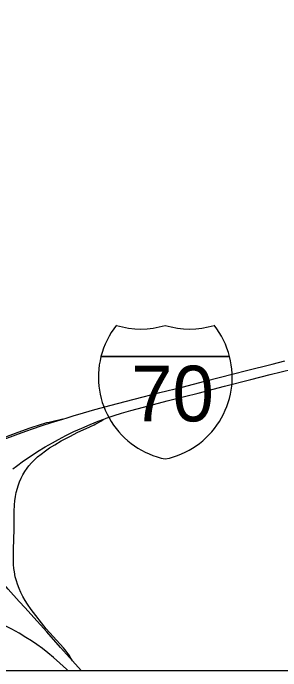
# Model space of a CAD drawing. Extents: x -29.6 to 34, y 0 to 22.
# Drawn here: x -22.655 to -22.122, y 1.053 to 2.363 of the extents above; entities that cross this region are included whole.
import ezdxf

# ---------------------------------------------------------------- set-up
doc = ezdxf.new("R2010")
doc.units = 0
for name, color, linetype in [('GM_X_Interchange_Ramps', 7, 'Continuous'), ('GM_X_Interstate_Route', 7, 'Continuous'), ('GM_X_Interstate_Shield', 7, 'Continuous'), ('SH_Text', 7, 'Continuous')]:
    doc.layers.add(name, color=color, linetype=linetype)

msp = doc.modelspace()

# ---------------------------------------------------------------- linework, layer by layer
at = {"layer": 'GM_X_Interchange_Ramps'}
for points in [[(-22.556, 1.5546), (-22.578, 1.5493), (-22.5835, 1.548), (-22.5887, 1.5468), (-22.5945, 1.5451), (-22.5995, 1.5435), (-22.6236, 1.5355), (-22.651, 1.5258), (-22.6817, 1.5148)], [(-22.5369, 1.0724), (-22.539, 1.0761), (-22.5414, 1.0803), (-22.5431, 1.0831), (-22.5453, 1.0864), (-22.5475, 1.0894), (-22.5497, 1.0923), (-22.555, 1.0984), (-22.5756, 1.1214), (-22.589, 1.1368), (-22.5986, 1.1485), (-22.6101, 1.1631), (-22.6192, 1.1752), (-22.6265, 1.1858), (-22.6311, 1.1932), (-22.6355, 1.2008), (-22.6397, 1.209), (-22.6432, 1.217), (-22.6464, 1.2252), (-22.6487, 1.2324), (-22.6508, 1.2402), (-22.6527, 1.25), (-22.6535, 1.2569), (-22.6541, 1.2644), (-22.6545, 1.2766), (-22.6543, 1.2953), (-22.6534, 1.3343), (-22.6529, 1.3704), (-22.6522, 1.3837), (-22.6515, 1.3918), (-22.6503, 1.4005), (-22.6488, 1.4085), (-22.6467, 1.417), (-22.6453, 1.4214), (-22.6423, 1.4296), (-22.639, 1.437), (-22.6355, 1.4437), (-22.6316, 1.4502), (-22.6273, 1.4565), (-22.6237, 1.4611), (-22.6184, 1.4673), (-22.6123, 1.4735), (-22.6063, 1.479), (-22.5992, 1.4849), (-22.5908, 1.4912), (-22.5826, 1.4969), (-22.5723, 1.5034), (-22.5591, 1.5109), (-22.5422, 1.52), (-22.5261, 1.5282), (-22.5098, 1.5359), (-22.4939, 1.5431), (-22.4901, 1.545), (-22.485, 1.5479), (-22.4806, 1.5505), (-22.4756, 1.5535), (-22.4725, 1.5553)]]:
    msp.add_lwpolyline(points, dxfattribs=at)
at = {"layer": 'GM_X_Interstate_Route'}
for points in [[(-22.4921, 1.5737), (-22.4894, 1.5745), (-22.4624, 1.5817), (-22.4139, 1.5941), (-22.3625, 1.6072), (-22.3185, 1.6184), (-22.2733, 1.6299), (-22.2163, 1.6444), (-22.1898, 1.6512), (-22.139, 1.6641), (-22.1136, 1.6705)], [(-22.3138, 1.5993), (-22.2866, 1.6063), (-22.2336, 1.6199), (-22.1817, 1.6332), (-22.1427, 1.6431), (-22.0993, 1.6543)], [(-22.4725, 1.5553), (-22.4698, 1.5563), (-22.4539, 1.5618), (-22.4389, 1.5666), (-22.4209, 1.5718), (-22.3956, 1.5785), (-22.3482, 1.5906), (-22.3138, 1.5993)], [(-22.556, 1.5546), (-22.5474, 1.5573), (-22.5352, 1.561), (-22.5151, 1.5671), (-22.4921, 1.5737)], [(-22.7877, 1.4729), (-22.7508, 1.4864), (-22.7151, 1.4991), (-22.6495, 1.5231), (-22.6298, 1.5302), (-22.599, 1.5408), (-22.5785, 1.5475), (-22.556, 1.5546)], [(-22.6557, 1.4554), (-22.6487, 1.4608), (-22.6345, 1.471), (-22.6215, 1.4799), (-22.6063, 1.4897), (-22.5914, 1.4989), (-22.5768, 1.5074), (-22.5646, 1.5141), (-22.5501, 1.5216), (-22.5339, 1.5296), (-22.5185, 1.5367), (-22.5019, 1.5439), (-22.4857, 1.5504), (-22.4725, 1.5553)], [(-22.5369, 1.0724), (-22.5609, 1.0993), (-22.5882, 1.1303), (-22.6197, 1.1654), (-22.6314, 1.1784), (-22.6428, 1.1908), (-22.6651, 1.2154), (-22.6865, 1.2393), (-22.6994, 1.2535), (-22.7087, 1.2639), (-22.7169, 1.273), (-22.7181, 1.2743), (-22.7279, 1.285), (-22.7381, 1.2962), (-22.7467, 1.3057), (-22.7553, 1.3152), (-22.7642, 1.3252), (-22.7693, 1.3308), (-22.7732, 1.3352), (-22.7743, 1.3365), (-22.7774, 1.3399), (-22.7814, 1.3444)], [(-22.5455, 1.0528), (-22.549, 1.0562), (-22.5618, 1.0681), (-22.575, 1.0796), (-22.5863, 1.0889), (-22.5969, 1.0971), (-22.6082, 1.1053), (-22.6188, 1.1125), (-22.6296, 1.1195), (-22.6431, 1.1276), (-22.6579, 1.1358), (-22.6724, 1.1433), (-22.6818, 1.1479), (-22.6966, 1.1547), (-22.7077, 1.1595)], [(-22.5191, 1.0528), (-22.5318, 1.0667), (-22.5369, 1.0724)]]:
    msp.add_lwpolyline(points, dxfattribs=at)
at = {"layer": 'GM_X_Interstate_Shield'}
for p, q in [((-22.48, 1.6789), (-22.2239, 1.6789)), ((-22.2239, 1.6789), (-22.48, 1.6789)), ((-22.2239, 1.6789), (-22.48, 1.6789))]:
    msp.add_line(p, q, dxfattribs=at)
for centre, start, end in [((-22.3187, 1.6381), 141.669, 165.8066), ((-22.4006, 1.9005), 253.0091, 286.9909), ((-22.3033, 1.9005), 253.0091, 286.9909), ((-22.3852, 1.6381), 14.1934, 38.331), ((-22.3187, 1.6381), 165.8066, 258.463), ((-22.3852, 1.6381), 281.537, 14.1934)]:
    msp.add_arc(centre, 0.1665, start, end, dxfattribs=at)
at = {"layer": 'SH_Text'}
msp.add_lwpolyline([(-29.5833, 13.2079), (-10.7478, 13.2079), (-10.7478, 1.0528), (-29.5833, 1.0528)], close=True, dxfattribs=at)

# ---------------------------------------------------------------- texts
at = {"layer": 'GM_X_Interstate_Shield'}
msp.add_text('70', height=0.11097, dxfattribs=at).set_placement((-22.4201, 1.5499))

doc.saveas('drawing.dxf')
